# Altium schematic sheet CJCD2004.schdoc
size 127 x 101 mm
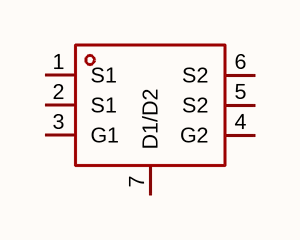
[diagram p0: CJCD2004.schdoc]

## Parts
Q?  cjcd2004  [DFNWB-6_L3.0-W2.0-P0.50-BL-EP]  (value not drawn)

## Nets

Not connected (* = marked no-connect by the designer): Q? 1(S1) 2(S1) 3(G1) 4(G2) 5(S2) 6(S2) 7(D1/D2)

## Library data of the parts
Q? = cjcd2004: 数量:2个N沟道;漏源电压(Vdss):20V;连续漏极电流(Id):10A;导通电阻(RDS(on)):7.3mΩ@4.5V;耗散功率(Pd):1.5W;阈值电压(Vgs(th)):400mV;; Manufacturer: CJ(江苏长电/长晶); AddInBom: yes; ModelId: 7fa8d8c781664c38a235ecb393a1b4ef; ModelTransform: 78.74,118.8974,0,0,0,0,0,0,0; Number: 2个N沟道; Drain to Source Voltage: 20V; Current - Continuous Drain(Id): 10A; Pd - Power Dissipation: 1.5W; Gate Threshold Voltage (Vgs(th)): 400mV; Gate Charge(Qg): 17nC@4.5V; Input Capacitance(Ciss): 1.95nF; Reverse Transfer Capacitance (Crss@Vds): 210pF; Configuration: 共漏; Type: N沟道; Output Capacitance(Coss): 250pF; Vgs: ±12V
